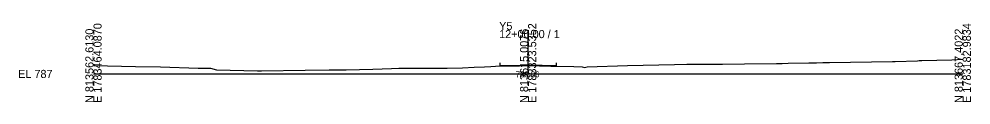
# Model space of a CAD drawing. Extents: x -26 to 1603, y -10 to 6526.
# Drawn here: x -25.7 to 302.8, y 2490.3 to 2517.9 of the extents above; entities that cross this region are included whole.
import ezdxf

# ---------------------------------------------------------------- set-up
doc = ezdxf.new("R2010")
doc.units = 0
for name, color, linetype in [('Exist Cross Section Cell', 7, 'Continuous'), ('Exist XS Center Line Elevation Label', 7, 'Continuous'), ('Exist XS Ground Line', 7, 'Continuous'), ('Prop XS Dump Level', 7, 'Continuous'), ('Prop XS EOT Tick Mark', 7, 'Continuous'), ('Prop XS Finish Grade Pavement', 7, 'Continuous')]:
    doc.layers.add(name, color=color, linetype=linetype)

msp = doc.modelspace()

# ---------------------------------------------------------------- linework, layer by layer
at = {"layer": 'Exist Cross Section Cell'}
for p, q in [((150, 2500), (150, 2515.13)), ((0, 2500), (150, 2500)), ((150, 2500), (300, 2500))]:
    msp.add_line(p, q, dxfattribs=at)
at = {"layer": 'Exist XS Ground Line'}
for p, q in [((217.07, 2503.34), (224.67, 2503.43)), ((224.67, 2503.43), (235.78, 2503.65)), ((235.78, 2503.65), (237.67, 2503.64)), ((237.67, 2503.64), (239.81, 2503.76)), ((239.81, 2503.76), (246.84, 2503.82)), ((246.84, 2503.82), (249.56, 2503.84)), ((249.56, 2503.84), (251.73, 2503.91)), ((251.73, 2503.91), (253.27, 2503.93)), ((253.27, 2503.93), (254.06, 2503.95)), ((254.06, 2503.95), (275.79, 2504.3)), ((275.79, 2504.3), (276.7, 2504.3)), ((276.7, 2504.3), (284.34, 2504.57)), ((284.34, 2504.57), (284.94, 2504.59)), ((284.94, 2504.59), (285.83, 2504.61)), ((285.83, 2504.61), (296.23, 2504.9)), ((296.23, 2504.9), (300, 2505.04)), ((0, 2502.88), (14.55, 2502.61)), ((14.55, 2502.61), (23.08, 2502.45)), ((23.08, 2502.45), (36.17, 2502.05)), ((36.17, 2502.05), (40.36, 2501.96)), ((40.36, 2501.96), (42.42, 2501.45)), ((42.42, 2501.45), (56.59, 2501.07)), ((56.59, 2501.07), (57.34, 2501.04)), ((57.34, 2501.04), (57.93, 2501.06)), ((57.93, 2501.06), (73.05, 2501.32)), ((73.05, 2501.32), (81.37, 2501.46)), ((81.37, 2501.46), (87.17, 2501.37)), ((87.17, 2501.37), (96.41, 2501.69)), ((96.41, 2501.69), (102.88, 2501.93)), ((102.88, 2501.93), (105.41, 2501.96)), ((105.41, 2501.96), (109.52, 2501.98)), ((109.52, 2501.98), (118.26, 2501.98)), ((118.26, 2501.98), (122.09, 2502.01)), ((122.09, 2502.01), (127.36, 2502.08)), ((127.36, 2502.08), (131.43, 2502.34)), ((131.43, 2502.34), (134.95, 2502.5)), ((134.95, 2502.5), (137.15, 2502.58)), ((137.15, 2502.58), (140.31, 2502.75)), ((140.31, 2502.75), (147.01, 2502.82)), ((147.01, 2502.82), (150.03, 2502.86)), ((150.03, 2502.86), (157.86, 2502.72)), ((157.86, 2502.72), (159.8, 2502.68)), ((159.8, 2502.68), (165.81, 2502.52)), ((165.81, 2502.52), (168.64, 2502.45)), ((168.64, 2502.45), (169.5, 2502.17)), ((169.5, 2502.17), (170.33, 2502.41)), ((170.33, 2502.41), (184.29, 2502.94)), ((184.29, 2502.94), (200.57, 2503.3)), ((200.57, 2503.3), (204.75, 2503.34)), ((204.75, 2503.34), (217.07, 2503.34))]:
    msp.add_line(p, q, dxfattribs=at)
at = {"layer": 'Prop XS Dump Level'}
for p, q in [((140.36, 2502.88), (150, 2502.98)), ((140.36, 2502.88), (150, 2502.98)), ((150, 2502.98), (159.81, 2502.81)), ((150, 2502.98), (159.81, 2502.81))]:
    msp.add_line(p, q, dxfattribs=at)
at = {"layer": 'Prop XS EOT Tick Mark'}
for p, q in [((140.36, 2502.88), (140.36, 2503.88)), ((159.81, 2502.81), (159.81, 2503.81))]:
    msp.add_line(p, q, dxfattribs=at)
at = {"layer": 'Prop XS Finish Grade Pavement'}
for p in [(140.36, 2502.88), (159.81, 2502.81)]:
    msp.add_line(p, (150, 2502.98), dxfattribs=at)

# ---------------------------------------------------------------- texts
at = {"layer": 'Exist Cross Section Cell'}
for s, p in [('E 1783464.0870', (2.8, 2490)), ('E 1783323.5352', (152.8, 2490)), ('E 1783182.9834', (302.8, 2490)), ('N 813562.6130', (0, 2490)), ('N 813615.0076', (150, 2490)), ('N 813667.4022', (300, 2490))]:
    msp.add_text(s, height=2.8, rotation=90, dxfattribs=at).set_placement(p)
for s, p in [('Y5', (140, 2515.13)), ('12+00.00 / 1', (140, 2512.33)), ('EL 787', (-26, 2498.6))]:
    msp.add_text(s, height=2.8, dxfattribs=at).set_placement(p)
at = {"layer": 'Exist XS Center Line Elevation Label'}
msp.add_text('789.86', height=2, dxfattribs=at).set_placement((145.73, 2498.86))

doc.saveas('drawing.dxf')
